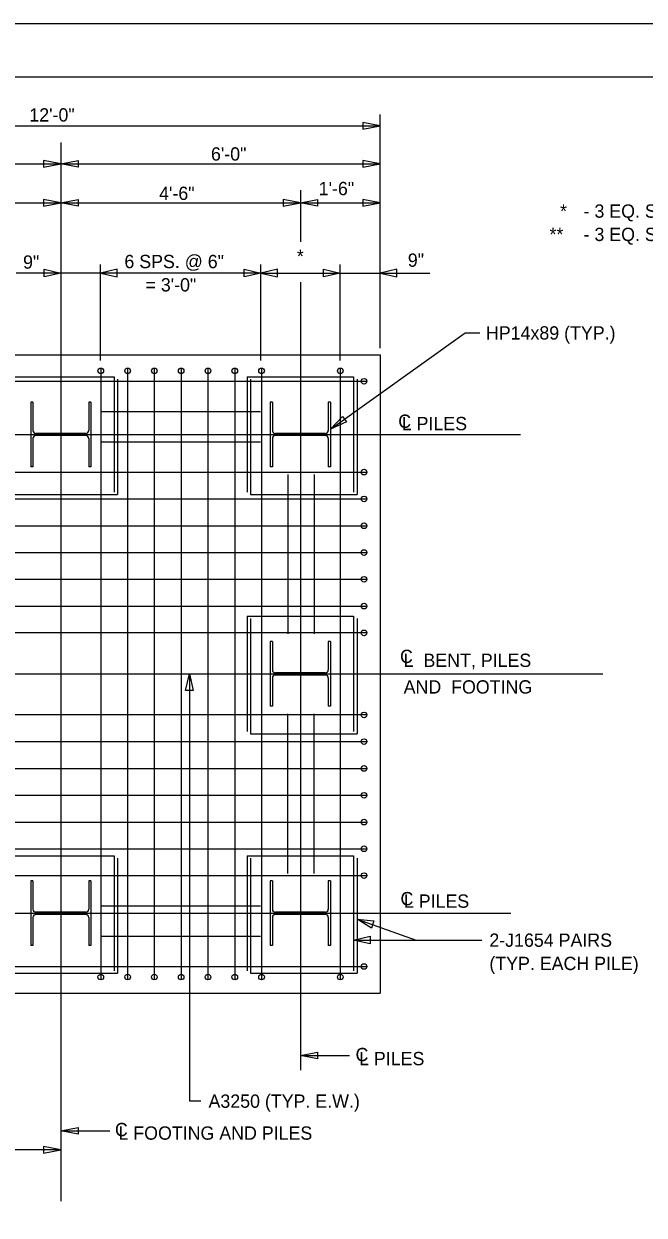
# Model space of a CAD drawing. Extents: x 1970675.2 to 1970711.3, y 796145.2 to 796167.2.
# Drawn here: x 1970693.86 to 1970699.69, y 796156.05 to 796167.25 of the extents above; entities that cross this region are included whole.
import ezdxf

# ---------------------------------------------------------------- set-up
doc = ezdxf.new("R2010")
doc.units = 0
for name, color, linetype in [('BR_AUTO DIMENSION', 7, 'Continuous'), ('BR_BORDER LINES', 7, 'Continuous'), ('BR_CENTER LINES', 7, 'Continuous'), ('BR_CONCRETE', 7, 'Continuous'), ('BR_REBAR', 7, 'Continuous'), ('BR_STRUCTURAL STEEL', 7, 'Continuous'), ('BR_TEXT', 7, 'Continuous'), ('Level 31', 7, 'Continuous')]:
    doc.layers.add(name, color=color, linetype=linetype)

msp = doc.modelspace()

# ---------------------------------------------------------------- linework, layer by layer
at = {"layer": 'BR_AUTO DIMENSION'}
for p, q in [((1970697.208, 796164.197), (1970697.208, 796166.393)), ((1970691.208, 796166.288), (1970697.208, 796166.288)), ((1970691.208, 796165.931), (1970694.208, 796165.931)), ((1970694.208, 796165.931), (1970697.208, 796165.931)), ((1970691.958, 796165.563), (1970694.208, 796165.563)), ((1970694.208, 796165.563), (1970696.458, 796165.563)), ((1970696.458, 796165.563), (1970697.208, 796165.563)), ((1970694.58, 796164.081), (1970694.58, 796164.984)), ((1970696.086, 796164.081), (1970696.086, 796164.984)), ((1970696.83, 796164.081), (1970696.83, 796164.984)), ((1970694.208, 796164.904), (1970693.787, 796164.904)), ((1970694.58, 796164.904), (1970694.208, 796164.904)), ((1970696.086, 796164.904), (1970694.58, 796164.904)), ((1970696.086, 796164.904), (1970696.83, 796164.904)), ((1970696.83, 796164.904), (1970697.208, 796164.904)), ((1970697.208, 796164.904), (1970697.673, 796164.904)), ((1970695.416, 796161.137), (1970695.416, 796157.125)), ((1970696.99, 796158.833), (1970697.546, 796158.635)), ((1970696.958, 796158.635), (1970698.162, 796158.635)), ((1970696.458, 796157.551), (1970696.919, 796157.551)), ((1970695.416, 796157.125), (1970695.523, 796157.125)), ((1970694.208, 796156.842), (1970694.669, 796156.842)), ((1970694.208, 796156.663), (1970693.656, 796156.663))]:
    msp.add_line(p, q, dxfattribs=at)
for points in [[(1970697.045, 796166.257), (1970697.208, 796166.288), (1970697.045, 796166.319)], [(1970694.045, 796165.9), (1970694.208, 796165.931), (1970694.045, 796165.962)], [(1970694.37, 796165.9), (1970694.208, 796165.931), (1970694.37, 796165.962)], [(1970697.045, 796165.9), (1970697.208, 796165.931), (1970697.045, 796165.962)], [(1970694.045, 796165.532), (1970694.208, 796165.563), (1970694.045, 796165.594)], [(1970694.37, 796165.532), (1970694.208, 796165.563), (1970694.37, 796165.594)], [(1970696.295, 796165.532), (1970696.458, 796165.563), (1970696.295, 796165.594)], [(1970696.62, 796165.532), (1970696.458, 796165.563), (1970696.62, 796165.594)], [(1970697.045, 796165.532), (1970697.208, 796165.563), (1970697.045, 796165.594)], [(1970694.052, 796164.94), (1970694.208, 796164.904), (1970694.052, 796164.868)], [(1970694.736, 796164.94), (1970694.58, 796164.904), (1970694.736, 796164.868)], [(1970695.93, 796164.94), (1970696.086, 796164.904), (1970695.93, 796164.868)], [(1970696.242, 796164.94), (1970696.086, 796164.904), (1970696.242, 796164.868)], [(1970696.674, 796164.94), (1970696.83, 796164.904), (1970696.674, 796164.868)], [(1970697.364, 796164.94), (1970697.208, 796164.904), (1970697.364, 796164.868)], [(1970696.892, 796163.505), (1970696.741, 796163.436), (1970696.855, 796163.556)], [(1970695.38, 796160.981), (1970695.416, 796161.137), (1970695.452, 796160.981)], [(1970697.125, 796158.747), (1970696.99, 796158.833), (1970697.149, 796158.815)], [(1970697.114, 796158.599), (1970696.958, 796158.635), (1970697.114, 796158.671)], [(1970696.62, 796157.52), (1970696.458, 796157.551), (1970696.62, 796157.583)], [(1970694.37, 796156.811), (1970694.208, 796156.842), (1970694.37, 796156.873)], [(1970694.045, 796156.632), (1970694.208, 796156.663), (1970694.045, 796156.695)]]:
    msp.add_lwpolyline(points, close=True, dxfattribs=at)
msp.add_lwpolyline([(1970696.741, 796163.436), (1970698.006, 796164.343), (1970698.143, 796164.343)], dxfattribs=at)
at = {"layer": 'BR_BORDER LINES'}
msp.add_line((1970710.736, 796166.746), (1970677.07, 796166.746), dxfattribs=at)
at = {"layer": 'BR_CENTER LINES'}
for p, q in [((1970694.208, 796166.13), (1970694.208, 796156.183)), ((1970696.458, 796165.684), (1970696.458, 796165.197)), ((1970696.458, 796164.819), (1970696.458, 796157.413)), ((1970689.58, 796163.387), (1970698.526, 796163.387)), ((1970689.025, 796161.137), (1970699.298, 796161.137)), ((1970689.58, 796158.887), (1970698.435, 796158.887))]:
    msp.add_line(p, q, dxfattribs=at)
at = {"layer": 'BR_CONCRETE'}
for p, q in [((1970691.208, 796164.137), (1970697.208, 796164.137)), ((1970697.208, 796164.137), (1970697.208, 796158.137)), ((1970691.208, 796158.137), (1970697.208, 796158.137))]:
    msp.add_line(p, q, dxfattribs=at)
at = {"layer": 'BR_REBAR'}
for p, q in [((1970693.708, 796163.928), (1970694.708, 796163.928)), ((1970694.583, 796164.012), (1970694.583, 796158.262)), ((1970694.708, 796163.928), (1970694.708, 796162.845)), ((1970694.74, 796163.906), (1970694.74, 796162.823)), ((1970694.835, 796164.012), (1970694.835, 796158.262)), ((1970695.086, 796164.012), (1970695.086, 796158.262)), ((1970695.338, 796164.012), (1970695.338, 796158.262)), ((1970695.59, 796164.012), (1970695.59, 796158.262)), ((1970695.842, 796164.012), (1970695.842, 796158.262)), ((1970695.958, 796163.928), (1970696.958, 796163.928)), ((1970695.958, 796163.928), (1970695.958, 796162.845)), ((1970695.99, 796163.906), (1970695.99, 796162.823)), ((1970696.093, 796164.012), (1970696.093, 796158.262)), ((1970696.833, 796164.012), (1970696.833, 796158.262)), ((1970696.958, 796163.928), (1970696.958, 796162.845)), ((1970696.99, 796163.906), (1970696.99, 796162.823)), ((1970691.333, 796163.887), (1970697.083, 796163.887)), ((1970694.583, 796163.602), (1970696.083, 796163.602)), ((1970694.583, 796163.317), (1970696.083, 796163.317)), ((1970691.333, 796163.033), (1970697.083, 796163.033)), ((1970696.34, 796163.012), (1970696.34, 796161.512)), ((1970696.586, 796163.012), (1970696.586, 796161.512)), ((1970694.208, 796162.928), (1970694.208, 796159.345)), ((1970693.74, 796162.823), (1970694.74, 796162.823)), ((1970695.99, 796162.823), (1970696.99, 796162.823)), ((1970691.333, 796162.781), (1970697.083, 796162.781)), ((1970691.333, 796162.529), (1970697.083, 796162.529)), ((1970691.333, 796162.277), (1970697.083, 796162.277)), ((1970691.333, 796162.026), (1970697.083, 796162.026)), ((1970691.333, 796161.774), (1970697.083, 796161.774)), ((1970695.958, 796161.678), (1970696.958, 796161.678)), ((1970695.958, 796161.678), (1970695.958, 796160.595)), ((1970696.958, 796161.678), (1970696.958, 796160.595)), ((1970695.99, 796161.656), (1970695.99, 796160.573)), ((1970696.99, 796161.656), (1970696.99, 796160.573)), ((1970697.083, 796161.522), (1970691.333, 796161.522)), ((1970692.416, 796161.137), (1970696, 796161.137)), ((1970697.083, 796160.751), (1970691.333, 796160.751)), ((1970696.34, 796159.262), (1970696.34, 796160.762)), ((1970696.586, 796159.262), (1970696.586, 796160.762)), ((1970695.99, 796160.573), (1970696.99, 796160.573)), ((1970691.333, 796160.5), (1970697.083, 796160.5)), ((1970691.333, 796160.248), (1970697.083, 796160.248)), ((1970691.333, 796159.996), (1970697.083, 796159.996)), ((1970691.333, 796159.744), (1970697.083, 796159.744)), ((1970691.333, 796159.493), (1970697.083, 796159.493)), ((1970693.708, 796159.428), (1970694.708, 796159.428)), ((1970694.708, 796159.428), (1970694.708, 796158.345)), ((1970695.958, 796159.428), (1970696.958, 796159.428)), ((1970695.958, 796159.428), (1970695.958, 796158.345)), ((1970696.958, 796159.428), (1970696.958, 796158.345)), ((1970694.74, 796159.406), (1970694.74, 796158.323)), ((1970695.99, 796159.406), (1970695.99, 796158.323)), ((1970696.99, 796159.406), (1970696.99, 796158.323)), ((1970691.333, 796159.241), (1970697.083, 796159.241)), ((1970694.583, 796158.956), (1970696.083, 796158.956)), ((1970694.583, 796158.671), (1970696.083, 796158.671)), ((1970691.333, 796158.387), (1970697.083, 796158.387)), ((1970693.74, 796158.323), (1970694.74, 796158.323)), ((1970695.99, 796158.323), (1970696.99, 796158.323))]:
    msp.add_line(p, q, dxfattribs=at)
for centre in [(1970694.583, 796163.985), (1970694.835, 796163.985), (1970695.086, 796163.985), (1970695.338, 796163.985), (1970695.59, 796163.985), (1970695.842, 796163.985), (1970696.093, 796163.985), (1970696.833, 796163.985), (1970697.056, 796163.887), (1970697.056, 796163.033), (1970697.056, 796162.781), (1970697.056, 796162.529), (1970697.056, 796162.277), (1970697.056, 796162.026), (1970697.056, 796161.774), (1970697.056, 796161.522), (1970697.056, 796160.751), (1970697.056, 796160.5), (1970697.056, 796160.248), (1970697.056, 796159.996), (1970697.056, 796159.744), (1970697.056, 796159.493), (1970697.056, 796159.241), (1970694.583, 796158.288), (1970694.835, 796158.288), (1970695.086, 796158.288), (1970695.338, 796158.288), (1970695.59, 796158.288), (1970695.842, 796158.288), (1970696.093, 796158.288), (1970696.833, 796158.288), (1970697.056, 796158.387)]:
    msp.add_circle(centre, 0.0265, dxfattribs=at)
at = {"layer": 'BR_STRUCTURAL STEEL'}
for p, q in [((1970693.925, 796163.691), (1970693.925, 796163.083)), ((1970693.945, 796163.691), (1970693.925, 796163.691)), ((1970693.945, 796163.691), (1970693.945, 796163.425)), ((1970694.47, 796163.691), (1970694.47, 796163.425)), ((1970694.491, 796163.691), (1970694.47, 796163.691)), ((1970694.491, 796163.691), (1970694.491, 796163.083)), ((1970696.175, 796163.691), (1970696.175, 796163.083)), ((1970696.195, 796163.691), (1970696.175, 796163.691)), ((1970696.195, 796163.691), (1970696.195, 796163.425)), ((1970696.72, 796163.691), (1970696.72, 796163.425)), ((1970696.741, 796163.691), (1970696.72, 796163.691)), ((1970696.741, 796163.691), (1970696.741, 796163.083)), ((1970693.945, 796163.348), (1970693.945, 796163.083)), ((1970694.442, 796163.397), (1970693.973, 796163.397)), ((1970694.442, 796163.376), (1970693.973, 796163.376)), ((1970694.47, 796163.348), (1970694.47, 796163.083)), ((1970696.195, 796163.348), (1970696.195, 796163.083)), ((1970696.692, 796163.397), (1970696.223, 796163.397)), ((1970696.692, 796163.376), (1970696.223, 796163.376)), ((1970696.72, 796163.348), (1970696.72, 796163.083)), ((1970693.945, 796163.083), (1970693.925, 796163.083)), ((1970694.491, 796163.083), (1970694.47, 796163.083)), ((1970696.195, 796163.083), (1970696.175, 796163.083)), ((1970696.741, 796163.083), (1970696.72, 796163.083)), ((1970696.175, 796161.441), (1970696.175, 796160.833)), ((1970696.195, 796161.441), (1970696.175, 796161.441)), ((1970696.195, 796161.441), (1970696.195, 796161.175)), ((1970696.72, 796161.441), (1970696.72, 796161.175)), ((1970696.741, 796161.441), (1970696.72, 796161.441)), ((1970696.741, 796161.441), (1970696.741, 796160.833)), ((1970696.692, 796161.147), (1970696.223, 796161.147)), ((1970696.692, 796161.126), (1970696.223, 796161.126)), ((1970696.195, 796161.098), (1970696.195, 796160.833)), ((1970696.72, 796161.098), (1970696.72, 796160.833)), ((1970696.195, 796160.833), (1970696.175, 796160.833)), ((1970696.741, 796160.833), (1970696.72, 796160.833)), ((1970693.925, 796159.191), (1970693.925, 796158.583)), ((1970693.945, 796159.191), (1970693.925, 796159.191)), ((1970693.945, 796159.191), (1970693.945, 796158.925)), ((1970694.47, 796159.191), (1970694.47, 796158.925)), ((1970694.491, 796159.191), (1970694.47, 796159.191)), ((1970694.491, 796159.191), (1970694.491, 796158.583)), ((1970696.175, 796159.191), (1970696.175, 796158.583)), ((1970696.195, 796159.191), (1970696.175, 796159.191)), ((1970696.195, 796159.191), (1970696.195, 796158.925)), ((1970696.72, 796159.191), (1970696.72, 796158.925)), ((1970696.741, 796159.191), (1970696.72, 796159.191)), ((1970696.741, 796159.191), (1970696.741, 796158.583)), ((1970694.442, 796158.897), (1970693.973, 796158.897)), ((1970694.442, 796158.876), (1970693.973, 796158.876)), ((1970696.692, 796158.897), (1970696.223, 796158.897)), ((1970696.692, 796158.876), (1970696.223, 796158.876)), ((1970693.945, 796158.848), (1970693.945, 796158.583)), ((1970694.47, 796158.848), (1970694.47, 796158.583)), ((1970696.195, 796158.848), (1970696.195, 796158.583)), ((1970696.72, 796158.848), (1970696.72, 796158.583)), ((1970693.945, 796158.583), (1970693.925, 796158.583)), ((1970694.491, 796158.583), (1970694.47, 796158.583)), ((1970696.195, 796158.583), (1970696.175, 796158.583)), ((1970696.741, 796158.583), (1970696.72, 796158.583))]:
    msp.add_line(p, q, dxfattribs=at)
for centre, start, end in [((1970693.973, 796163.425), 180, 270), ((1970693.973, 796163.348), 90, 180), ((1970694.442, 796163.425), 270, 360), ((1970694.442, 796163.348), 360, 90), ((1970696.223, 796163.425), 180, 270), ((1970696.223, 796163.348), 90, 180), ((1970696.692, 796163.425), 270, 360), ((1970696.692, 796163.348), 360, 90), ((1970696.223, 796161.175), 180, 270), ((1970696.223, 796161.098), 90, 180), ((1970696.692, 796161.175), 270, 360), ((1970696.692, 796161.098), 360, 90), ((1970693.973, 796158.925), 180, 270), ((1970693.973, 796158.848), 90, 180), ((1970694.442, 796158.925), 270, 360), ((1970694.442, 796158.848), 360, 90), ((1970696.223, 796158.925), 180, 270), ((1970696.223, 796158.848), 90, 180), ((1970696.692, 796158.925), 270, 360), ((1970696.692, 796158.848), 360, 90)]:
    msp.add_arc(centre, 0.0281, start, end, dxfattribs=at)
at = {"layer": 'Level 31'}
msp.add_lwpolyline([(1970675.236, 796145.246), (1970711.236, 796145.246), (1970711.236, 796167.246), (1970675.236, 796167.246)], close=True, dxfattribs=at)

# ---------------------------------------------------------------- texts
at = {"layer": 'BR_AUTO DIMENSION'}
for s, p in [('12\'-0"', (1970693.912, 796166.328)), ('6\'-0"', (1970695.618, 796165.961)), ('C', (1970697.377, 796163.449)), ('C', (1970697.394, 796161.239)), ('C', (1970697.398, 796158.962)), ('C', (1970696.976, 796157.497)), ('C', (1970694.716, 796156.792))]:
    msp.add_text(s, height=0.125, dxfattribs=at).set_placement(p)
at = {"layer": 'BR_TEXT'}
for s, p in [('4\'-6"', (1970695.131, 796165.591)), ('1\'-6"', (1970696.63, 796165.636)), ('- 3 EQ. SPS. = 1\'-6"', (1970699.118, 796165.424)), ('- 3 EQ. SPS. = 1\'-8 3/4"', (1970699.118, 796165.205)), ('6 SPS. @ 6"', (1970694.805, 796164.95)), ('= 3\'-0"', (1970695.003, 796164.731)), ('HP14x89 (TYP.)', (1970698.201, 796164.279)), ('L PILES', (1970697.41, 796163.427)), ('L  BENT, PILES', (1970697.428, 796161.202)), ('AND  FOOTING', (1970697.428, 796160.952)), ('L PILES', (1970697.43, 796158.939)), ('2-J1654 PAIRS', (1970698.233, 796158.572)), ('(TYP. EACH PILE)', (1970698.233, 796158.353)), ('L PILES', (1970697.009, 796157.459)), ('A3250 (TYP. E.W.)', (1970695.595, 796157.059)), ('L FOOTING AND PILES', (1970694.749, 796156.759))]:
    msp.add_text(s, height=0.125, dxfattribs=at).set_placement(p)
for s, p in [('*', (1970698.897, 796165.424)), ('**', (1970698.798, 796165.205)), ('9"', (1970693.853, 796164.945)), ('*', (1970696.425, 796164.999)), ('9"', (1970697.467, 796164.963))]:
    msp.add_text(s, height=0.125, rotation=360, dxfattribs=at).set_placement(p)

doc.saveas('drawing.dxf')
